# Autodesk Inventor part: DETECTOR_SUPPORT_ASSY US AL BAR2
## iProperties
Shininess: 64.0
Length Units: 11272
Angle Units: 11279
Time Units: 11290
Mass Units: 11286
Length Display Precision: 3
Angle Display Precision: 2
Compacted: True
Part Number: DETECTOR_SUPPORT_ASSY US AL BAR2
Document SubType Name: Modeling
Created: 2004-08
Designer: John Blackburn
Material: ALUMINUM
Manufacturer: Standard
Standards Organization: Custom
Density: 0.0
Volumn: 0.0
Area: 0.0
PropertySet Name: Model Information
Control State: 0
Master: False
Checked Out: False
Author: John Blackburn
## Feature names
1. ExtrusionBlind1
2. AM_HOLE_SI0029_1 [Hole]
3. Rectangular Pattern1
